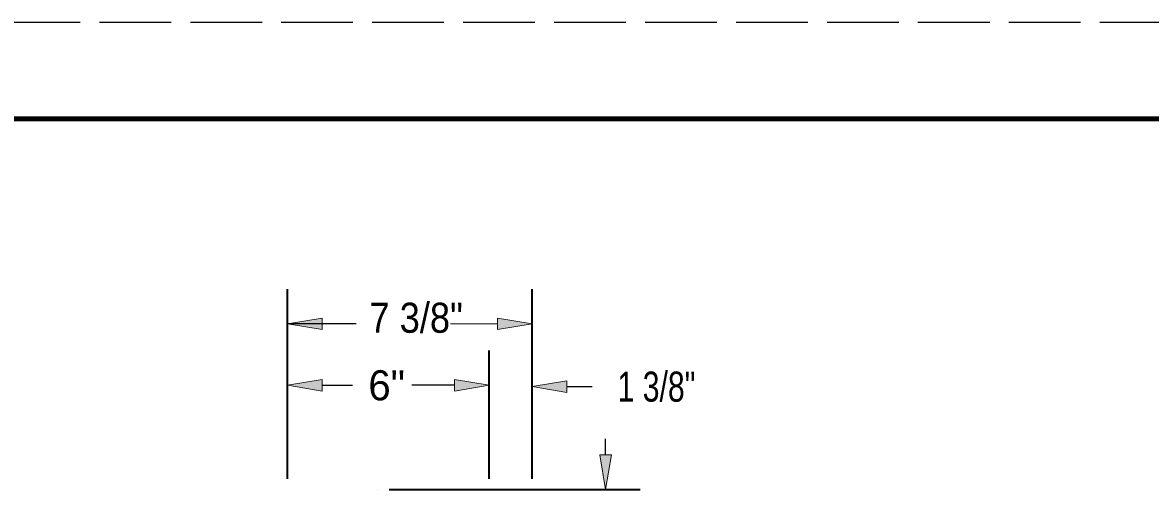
# Model space of a CAD drawing. Extents: x 36.6 to 71.9, y 0.8 to 22.8.
# Drawn here: x 54.49 to 60.35, y 20.35 to 22.78 of the extents above; entities that cross this region are included whole.
import ezdxf

# ---------------------------------------------------------------- set-up
doc = ezdxf.new("R2010")
doc.units = 0
doc.header["$LTSCALE"] = 0.062
doc.linetypes.add('LONG_DASHED', pattern=[7.5, 6, -1.5])
for name, color, linetype, lineweight in [('1', 7, 'Continuous', 13), ('3', 7, 'Continuous', 25), ('8', 7, 'Continuous', 13)]:
    doc.layers.add(name, color=color, linetype=linetype, lineweight=lineweight)

msp = doc.modelspace()

# ---------------------------------------------------------------- hatches: boundary and pattern name
at = {"layer": '1'}
for points in [[(56.04975, 21.18342), (56.04975, 21.24333), (55.86975, 21.21342), (55.86975, 21.21342)], [(56.959, 21.18342), (56.959, 21.24333), (57.139, 21.21342), (57.139, 21.21342)], [(56.04967, 20.86433), (56.04967, 20.92433), (55.86967, 20.89433), (55.86967, 20.89433)], [(56.737, 20.86433), (56.737, 20.92433), (56.91692, 20.89433), (56.91692, 20.89433)], [(57.5505, 20.53317), (57.49042, 20.53317), (57.5205, 20.35317), (57.5205, 20.35317)]]:
    msp.add_hatch(color=256, dxfattribs=at).paths.add_polyline_path(points)
at = {"layer": '3'}
msp.add_hatch(color=256, dxfattribs=at).paths.add_polyline_path([(57.319, 20.85742), (57.319, 20.91742), (57.139, 20.88742), (57.139, 20.88742)])

# ---------------------------------------------------------------- linework, layer by layer
at = {"layer": '1', "linetype": 'LONG_DASHED', "lineweight": 25}
msp.add_line((71.78558, 22.77842), (36.58558, 22.77842), dxfattribs=at)
at = {"layer": '1', "lineweight": 158}
msp.add_line((71.70225, 22.27842), (39.20225, 22.27842), dxfattribs=at)
at = {"layer": '1', "lineweight": 35}
for p, q in [((55.86975, 20.70025), (55.86975, 21.39342)), ((57.139, 20.40842), (57.139, 21.39342)), ((55.86967, 20.40842), (55.86967, 21.07433)), ((56.917, 20.40842), (56.917, 21.07433)), ((56.39692, 20.35325), (57.7005, 20.35325))]:
    msp.add_line(p, q, dxfattribs=at)
at = {"layer": '1', "lineweight": 25}
for p, q in [((56.22675, 21.21342), (55.86975, 21.21342)), ((56.04967, 20.89433), (56.20692, 20.89433)), ((56.737, 20.89433), (56.51425, 20.89433)), ((57.5205, 20.53325), (57.5205, 20.61683))]:
    msp.add_line(p, q, dxfattribs=at)
at = {"layer": '1'}
msp.add_line((56.959, 21.21342), (56.71533, 21.21342), dxfattribs=at)
for points in [[(56.04975, 21.18342), (56.04975, 21.24333), (55.86975, 21.21342), (55.86975, 21.21342)], [(56.959, 21.18342), (56.959, 21.24333), (57.139, 21.21342), (57.139, 21.21342)], [(56.04967, 20.86433), (56.04967, 20.92433), (55.86967, 20.89433), (55.86967, 20.89433)], [(56.737, 20.86433), (56.737, 20.92433), (56.91692, 20.89433), (56.91692, 20.89433)], [(57.5505, 20.53317), (57.49042, 20.53317), (57.5205, 20.35317), (57.5205, 20.35317)]]:
    msp.add_lwpolyline(points, close=True, dxfattribs=at)
at = {"layer": '3'}
msp.add_line((57.319, 20.88742), (57.45117, 20.88742), dxfattribs=at)
at = {"layer": '3', "lineweight": 13}
msp.add_lwpolyline([(57.319, 20.85742), (57.319, 20.91742), (57.139, 20.88742), (57.139, 20.88742)], close=True, dxfattribs=at)
at = {"layer": '8'}
for p, q in [((57.139, 21.21342), (57.13908, 21.21342)), ((56.917, 20.89433), (56.91708, 20.89433)), ((55.86975, 20.63775), (55.86983, 20.63775)), ((56.33442, 20.35325), (56.3345, 20.35325))]:
    msp.add_line(p, q, dxfattribs=at)

# ---------------------------------------------------------------- texts
at = {"layer": '1', "width": 0.9}
msp.add_text('7 3/8"', height=0.1562, dxfattribs=at).set_placement((56.29517, 21.16708))
at = {"layer": '1'}
msp.add_text('6"', height=0.1562, dxfattribs=at).set_placement((56.28917, 20.81625))
at = {"layer": '3', "width": 0.75}
msp.add_text('1 3/8"', height=0.1562, dxfattribs=at).set_placement((57.58258, 20.80925))

doc.saveas('drawing.dxf')
